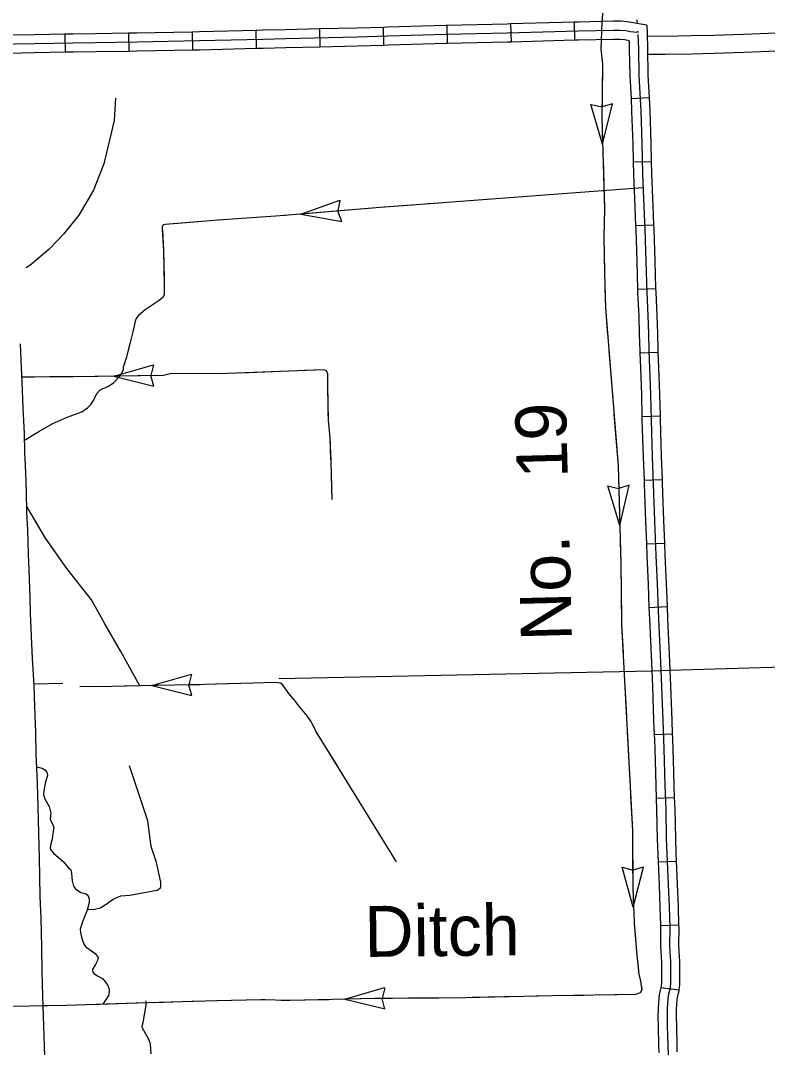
# Model space of a CAD drawing. Extents: x -117616 to 64730, y 54117 to 789866.
# Drawn here: x 62461.2 to 62585, y 54561.1 to 54731.4 of the extents above; entities that cross this region are included whole.
import ezdxf

# ---------------------------------------------------------------- set-up
doc = ezdxf.new("R2010")
doc.units = 0
for name, color, linetype in [('10', 7, 'Continuous'), ('32', 7, 'Continuous'), ('34', 7, 'Continuous'), ('35', 7, 'Continuous'), ('43', 7, 'Continuous'), ('46', 7, 'Continuous'), ('5', 7, 'Continuous')]:
    doc.layers.add(name, color=color, linetype=linetype)

msp = doc.modelspace()

# ---------------------------------------------------------------- linework, layer by layer
at = {"layer": '10'}
for points in [[(62463.45, 54621.13), (62463.17, 54625.64), (62463.03, 54629.31), (62462.86, 54633.17), (62462.8, 54635.73), (62462.61, 54640.27), (62462.52, 54642.92), (62462.37, 54646.97), (62462.25, 54649.9), (62462.17, 54653.28), (62462.08, 54656.55), (62461.9, 54659.8), (62461.85, 54662.96), (62461.61, 54667.13), (62461.46, 54671.55), (62461.34, 54673.84), (62461.16, 54677.81)], [(62465.35, 54556.4), (62465.1, 54562.98), (62464.96, 54568.04), (62464.9, 54569.68), (62464.75, 54573.76), (62464.71, 54577.71), (62464.61, 54582.54), (62464.45, 54586.14), (62464.37, 54589.4), (62464.35, 54592.54), (62464.23, 54596.68), (62464.1, 54600.96), (62464.01, 54604.98), (62463.8, 54609.81), (62463.73, 54613.37), (62463.56, 54617.65), (62463.45, 54621.13)]]:
    msp.add_lwpolyline(points, dxfattribs=at)
at = {"layer": '32'}
for p, q in [((62542.41, 54730.87), (62542.49, 54727.87)), ((62552.96, 54731.16), (62553.04, 54728.16)), ((62468.52, 54729.17), (62468.57, 54726.17)), ((62479.08, 54729.33), (62479.13, 54726.33)), ((62489.64, 54729.53), (62489.69, 54726.53)), ((62500.18, 54729.79), (62500.26, 54726.79)), ((62510.74, 54730.04), (62510.81, 54727.04)), ((62521.29, 54730.31), (62521.38, 54727.31)), ((62531.85, 54730.63), (62531.92, 54727.63)), ((62563.54, 54729.7), (62563.54, 54729.47)), ((62562.38, 54718.51), (62565.38, 54718.67)), ((62562.75, 54708), (62565.75, 54708.08)), ((62563.14, 54697.42), (62566.13, 54697.55)), ((62563.46, 54686.89), (62566.46, 54686.97)), ((62563.85, 54676.33), (62566.85, 54676.43)), ((62564.19, 54665.79), (62567.19, 54665.86)), ((62564.54, 54655.21), (62567.54, 54655.33)), ((62564.93, 54644.66), (62567.93, 54644.78)), ((62565.35, 54634.11), (62568.35, 54634.23)), ((62565.84, 54623.56), (62568.83, 54623.68)), ((62566.23, 54613), (62569.23, 54613.13)), ((62566.56, 54602.46), (62569.56, 54602.56)), ((62566.88, 54591.89), (62569.87, 54592.02)), ((62567.27, 54581.36), (62570.27, 54581.45)), ((62567.34, 54571.06), (62570.32, 54570.66))]:
    msp.add_line(p, q, dxfattribs=at)
for points in [[(62542.41, 54730.87), (62541.84, 54730.86), (62531.85, 54730.63)], [(62552.96, 54731.16), (62542.41, 54730.87)], [(62565.03, 54730.67), (62561.73, 54731.2), (62560.7, 54731.31), (62559.46, 54731.31), (62553.62, 54731.18), (62552.96, 54731.16)], [(62563.54, 54729.47), (62562.84, 54729.52), (62562.32, 54729.58), (62561.53, 54729.71), (62560.61, 54729.81), (62559.48, 54729.81), (62553.66, 54729.68), (62541.88, 54729.36), (62531.73, 54729.12), (62522.09, 54728.84), (62516.97, 54728.68), (62505.15, 54728.41), (62501.37, 54728.32), (62490.87, 54728.05), (62480.51, 54727.85), (62473.64, 54727.75), (62469.9, 54727.69), (62463.5, 54727.58), (62456.91, 54727.46)], [(62468.52, 54729.17), (62463.47, 54729.08), (62459.35, 54729)], [(62479.08, 54729.33), (62473.62, 54729.25), (62469.88, 54729.19), (62468.52, 54729.17)], [(62489.64, 54729.53), (62480.48, 54729.35), (62479.08, 54729.33)], [(62500.18, 54729.79), (62490.84, 54729.55), (62489.64, 54729.53)], [(62510.74, 54730.04), (62505.11, 54729.91), (62501.33, 54729.82), (62500.18, 54729.79)], [(62521.29, 54730.31), (62516.93, 54730.18), (62510.74, 54730.04)], [(62531.85, 54730.63), (62531.69, 54730.62), (62522.04, 54730.34), (62521.29, 54730.31)], [(62563.54, 54729.15), (62563.6, 54726.77), (62563.68, 54722.31), (62563.99, 54716.44), (62564.17, 54711.08), (62564.3, 54706.01), (62564.5, 54700.6), (62564.67, 54696.77), (62564.84, 54691.51), (62564.98, 54686.33), (62565.18, 54682.51), (62565.26, 54679.45), (62565.34, 54676.67), (62565.43, 54673.83), (62565.61, 54669.44), (62565.7, 54665.22), (62565.88, 54659.09), (62566.07, 54654.57), (62566.29, 54648.48), (62566.51, 54642.7), (62566.7, 54637.99), (62566.93, 54632.15), (62567.23, 54626.23), (62567.44, 54621.01), (62567.63, 54615.35), (62567.76, 54612.32), (62567.88, 54608.73), (62568, 54604.58), (62568.13, 54600.59), (62568.23, 54595.75), (62568.32, 54593.21), (62568.54, 54588.15), (62568.68, 54584.43), (62568.79, 54580.94), (62568.75, 54577.99), (62568.94, 54575.33), (62568.94, 54572.54), (62568.93, 54571.64), (62568.88, 54571.22), (62568.81, 54570.72), (62568.67, 54570.19), (62568.54, 54569.65), (62568.5, 54569.17), (62568.36, 54567.55), (62568.35, 54566), (62568.4, 54564.76), (62568.46, 54561.4), (62568.58, 54558.43)], [(62565.03, 54730.67), (62565.04, 54729.19)], [(62565.04, 54729.19), (62565.1, 54726.8), (62565.18, 54722.36), (62565.38, 54718.67)], [(62531.92, 54727.63), (62531.77, 54727.63), (62522.13, 54727.34), (62521.38, 54727.31)], [(62542.49, 54727.87), (62541.91, 54727.86), (62531.92, 54727.63)], [(62553.04, 54728.16), (62542.49, 54727.87)], [(62562.07, 54728.1), (62561.33, 54728.22), (62560.53, 54728.31), (62559.49, 54728.31), (62553.7, 54728.18), (62553.04, 54728.16)], [(62562.07, 54728.1), (62562.1, 54726.73), (62562.18, 54722.25), (62562.38, 54718.51)], [(62468.57, 54726.17), (62463.52, 54726.08), (62459.43, 54726)], [(62479.13, 54726.33), (62473.66, 54726.25), (62469.93, 54726.19), (62468.57, 54726.17)], [(62489.69, 54726.53), (62480.54, 54726.35), (62479.13, 54726.33)], [(62500.26, 54726.79), (62490.9, 54726.55), (62489.69, 54726.53)], [(62510.81, 54727.04), (62505.18, 54726.91), (62501.41, 54726.82), (62500.26, 54726.79)], [(62521.38, 54727.31), (62517.01, 54727.18), (62510.81, 54727.04)], [(62562.38, 54718.51), (62562.49, 54716.38), (62562.67, 54711.03), (62562.75, 54708)], [(62565.38, 54718.67), (62565.49, 54716.51), (62565.67, 54711.12), (62565.75, 54708.08)], [(62562.75, 54708), (62562.8, 54705.96), (62563, 54700.54), (62563.14, 54697.42)], [(62565.75, 54708.08), (62565.8, 54706.05), (62566, 54700.66), (62566.13, 54697.55)], [(62563.14, 54697.42), (62563.17, 54696.71), (62563.34, 54691.46), (62563.46, 54686.89)], [(62566.13, 54697.55), (62566.17, 54696.83), (62566.33, 54691.55), (62566.46, 54686.97)], [(62563.46, 54686.89), (62563.48, 54686.27), (62563.69, 54682.45), (62563.76, 54679.41), (62563.84, 54676.63), (62563.85, 54676.33)], [(62566.46, 54686.97), (62566.48, 54686.39), (62566.68, 54682.57), (62566.76, 54679.49), (62566.84, 54676.72), (62566.85, 54676.43)], [(62563.85, 54676.33), (62563.93, 54673.78), (62564.11, 54669.39), (62564.19, 54665.79)], [(62566.85, 54676.43), (62566.93, 54673.89), (62567.11, 54669.48), (62567.19, 54665.86)], [(62564.19, 54665.79), (62564.2, 54665.18), (62564.39, 54659.03), (62564.54, 54655.21)], [(62567.19, 54665.86), (62567.2, 54665.26), (62567.38, 54659.14), (62567.54, 54655.33)], [(62564.54, 54655.21), (62564.57, 54654.52), (62564.79, 54648.42), (62564.93, 54644.66)], [(62567.54, 54655.33), (62567.56, 54654.63), (62567.79, 54648.53), (62567.93, 54644.78)], [(62564.93, 54644.66), (62565.01, 54642.64), (62565.2, 54637.93), (62565.35, 54634.11)], [(62567.93, 54644.78), (62568.01, 54642.76), (62568.2, 54638.05), (62568.35, 54634.23)], [(62565.35, 54634.11), (62565.44, 54632.09), (62565.73, 54626.16), (62565.84, 54623.56)], [(62568.35, 54634.23), (62568.43, 54632.22), (62568.73, 54626.29), (62568.83, 54623.68)], [(62565.84, 54623.56), (62565.94, 54620.96), (62566.13, 54615.29), (62566.23, 54613)], [(62568.83, 54623.68), (62568.94, 54621.07), (62569.13, 54615.4), (62569.23, 54613.13)], [(62566.23, 54613), (62566.26, 54612.27), (62566.38, 54608.69), (62566.5, 54604.54), (62566.56, 54602.46)], [(62569.23, 54613.13), (62569.26, 54612.38), (62569.38, 54608.78), (62569.5, 54604.63), (62569.56, 54602.56)], [(62566.56, 54602.46), (62566.63, 54600.55), (62566.73, 54595.71), (62566.82, 54593.15), (62566.88, 54591.89)], [(62569.56, 54602.56), (62569.63, 54600.63), (62569.73, 54595.79), (62569.82, 54593.27), (62569.87, 54592.02)], [(62566.88, 54591.89), (62567.04, 54588.09), (62567.18, 54584.38), (62567.27, 54581.36)], [(62569.87, 54592.02), (62570.04, 54588.21), (62570.18, 54584.48), (62570.27, 54581.45)], [(62567.27, 54581.36), (62567.29, 54580.93), (62567.25, 54577.94), (62567.44, 54575.27), (62567.44, 54572.55), (62567.43, 54571.75), (62567.39, 54571.4), (62567.34, 54571.06)], [(62570.27, 54581.45), (62570.29, 54580.95), (62570.25, 54578.03), (62570.44, 54575.38), (62570.44, 54572.53), (62570.43, 54571.54), (62570.37, 54571.03), (62570.32, 54570.66)], [(62567.34, 54571.06), (62567.34, 54571.02), (62567.22, 54570.56), (62567.05, 54569.88), (62567.01, 54569.29), (62566.86, 54567.62), (62566.85, 54565.98), (62566.9, 54564.71), (62566.96, 54561.36), (62567.01, 54560.29)], [(62570.32, 54570.66), (62570.29, 54570.43), (62570.12, 54569.82), (62570.03, 54569.41), (62570, 54569.04), (62569.86, 54567.47), (62569.85, 54566.03), (62569.9, 54564.8), (62569.96, 54561.44), (62570, 54560.4)]]:
    msp.add_lwpolyline(points, dxfattribs=at)
at = {"layer": '34'}
msp.add_lwpolyline([(62563.45, 54730.92), (62563.4, 54731.57)], dxfattribs=at)
at = {"layer": '35'}
for points in [[(62476.94, 54718.55), (62476.69, 54714.86), (62474.97, 54707.66), (62473.31, 54703.29), (62470.85, 54699.17), (62468.33, 54696.03), (62465.87, 54693.45), (62462.98, 54691.05), (62462.12, 54690.43)], [(62461.87, 54661.82), (62464.24, 54663.28), (62466.41, 54664.56), (62468.89, 54665.64), (62471.34, 54666.53), (62472.3, 54667.21), (62472.85, 54667.75), (62473.3, 54668.44), (62473.61, 54669.12), (62473.87, 54669.66), (62474.36, 54670.15), (62474.81, 54670.43), (62475.32, 54670.58), (62475.78, 54670.78), (62476.63, 54671.43), (62477.69, 54672.52), (62478.23, 54673.51), (62478.27, 54674.09)], [(62480.97, 54621.11), (62477.82, 54626.81), (62475.18, 54631.37), (62472.96, 54635.37), (62468.84, 54640.55), (62465.31, 54645.57), (62462.23, 54650.86)], [(62463.89, 54607.66), (62464.77, 54607.44), (62465.22, 54607.18), (62465.54, 54606.8), (62465.63, 54606.2), (62465.35, 54605.15), (62465.05, 54603.75), (62465.01, 54603.09), (62465.24, 54602.36), (62465.93, 54601.09), (62466.2, 54599.97), (62466.12, 54598.91), (62466.51, 54598.18), (62466.68, 54597.58), (62466.61, 54596.94), (62466.44, 54595.7), (62466.21, 54594.9), (62466.12, 54594.16), (62466.29, 54593.77), (62466.66, 54593.34), (62468.24, 54591.97)], [(62472.27, 54583.97), (62473.44, 54584.06), (62474.37, 54584.26), (62475.23, 54584.77), (62476.55, 54585.7), (62477.8, 54586.25), (62479.32, 54586.4), (62482, 54586.87), (62483.84, 54587.22), (62484.42, 54587.65), (62484.46, 54588.51), (62483.72, 54591.78), (62482.82, 54594.44), (62482.28, 54598.69), (62480.45, 54604.18), (62479.24, 54607.81)], [(62468.24, 54591.97), (62469.14, 54590.91), (62469.51, 54590.56), (62469.66, 54589.96), (62469.75, 54588.75), (62469.96, 54587.89), (62470.31, 54587.4), (62471.19, 54586.82), (62471.95, 54586.64), (62472.36, 54586.36), (62472.55, 54585.78), (62472.55, 54585.16), (62472.25, 54583.9), (62471.49, 54582.1), (62471.09, 54580.72), (62471.13, 54580.2), (62471.34, 54579.21), (62471.69, 54578.24), (62471.97, 54577.87), (62472.79, 54577.25), (62473.57, 54576.71), (62474.04, 54576.02), (62473.93, 54575.54), (62473.63, 54574.85), (62473.12, 54574.1), (62473.09, 54573.77), (62473.33, 54573.38), (62473.96, 54572.99), (62474.8, 54572.54), (62475.27, 54571.97), (62475.66, 54571.38), (62475.9, 54570.72), (62475.9, 54570.36), (62475.75, 54569.73), (62475.36, 54569.13), (62474.84, 54568.27)], [(62482.82, 54560.06), (62482.72, 54561.68), (62482.48, 54562.46), (62481.9, 54563.45), (62481.6, 54563.95), (62481.39, 54564.29), (62481.36, 54564.67), (62481.53, 54565.24), (62482.04, 54568.12), (62482.04, 54568.87)]]:
    msp.add_lwpolyline(points, dxfattribs=at)
at = {"layer": '43'}
for p, q in [((62555.74, 54717.54), (62557.58, 54717.11)), ((62557.68, 54710.96), (62555.74, 54717.54)), ((62559.29, 54717.63), (62557.6, 54717.11)), ((62557.68, 54710.96), (62559.29, 54717.63)), ((62507.67, 54699.35), (62514.13, 54701.65)), ((62514.13, 54701.65), (62513.8, 54699.85)), ((62507.67, 54699.35), (62514.42, 54698.11)), ((62514.42, 54698.11), (62513.81, 54699.83)), ((62476.63, 54672.46), (62483.23, 54674.34)), ((62483.23, 54674.34), (62482.79, 54672.57)), ((62476.63, 54672.46), (62483.29, 54670.79)), ((62483.29, 54670.79), (62482.79, 54672.54)), ((62560.52, 54647.69), (62558.55, 54654.27)), ((62558.55, 54654.27), (62560.33, 54653.85)), ((62562.1, 54654.37), (62560.35, 54653.85)), ((62560.52, 54647.69), (62562.1, 54654.37)), ((62482.93, 54621.14), (62489.53, 54623.02)), ((62489.53, 54623.03), (62489.09, 54621.26)), ((62482.93, 54621.14), (62489.59, 54619.47)), ((62489.59, 54619.48), (62489.09, 54621.23)), ((62562.72, 54584.38), (62560.89, 54591)), ((62560.89, 54591), (62562.66, 54590.54)), ((62564.44, 54591.03), (62562.68, 54590.54)), ((62562.72, 54584.38), (62564.44, 54591.03)), ((62514.95, 54569.11), (62521.53, 54571.06)), ((62521.57, 54571.03), (62521.11, 54569.26)), ((62514.95, 54569.11), (62521.62, 54567.5)), ((62521.59, 54567.47), (62521.11, 54569.23))]:
    msp.add_line(p, q, dxfattribs=at)
for points in [[(62557.87, 54735.19), (62557.57, 54731.24), (62557.37, 54726.69), (62557.67, 54724.22), (62557.57, 54715.33), (62557.96, 54700.12), (62557.87, 54695.57), (62557.96, 54689.55), (62558.16, 54683.72), (62560.23, 54657.64), (62560.7, 54641.38), (62560.82, 54631.27), (62562.61, 54597.12), (62562.69, 54587.57), (62562.92, 54581.79), (62563.31, 54576.99), (62563.69, 54573.27), (62563.98, 54572.11), (62564.09, 54571.33), (62564.15, 54570.69), (62563.92, 54570.19), (62563.12, 54569.88), (62549.35, 54569.67), (62535, 54569.37), (62530.54, 54569.31), (62519.98, 54569.24), (62505.82, 54568.88), (62501.04, 54569.04), (62493.73, 54568.85), (62480.38, 54568.45), (62468.72, 54568.06), (62459.7, 54567.93)], [(62557.44, 54728.26), (62557.37, 54726.69), (62557.67, 54724.22), (62557.64, 54721.51)], [(62557.61, 54718.87), (62557.57, 54715.33), (62557.68, 54710.96)], [(62557.75, 54708.32), (62557.85, 54704.36)], [(62564.26, 54703.68), (62528.96, 54701.03), (62520.81, 54700.41), (62504.24, 54699.07), (62493.23, 54698.26), (62485.17, 54697.61), (62484.9, 54697.55), (62484.78, 54697.43), (62484.69, 54697.19), (62484.69, 54696.84), (62484.9, 54693.23), (62485.02, 54687.63), (62485.02, 54685.97), (62484.84, 54685.58), (62484.19, 54684.98), (62481.87, 54683.47), (62480.74, 54682.51), (62480.41, 54682.13), (62480.2, 54681.59), (62479.78, 54679.8), (62478.74, 54675.6), (62478.27, 54674.09)], [(62557.85, 54704.36), (62557.96, 54700.4)], [(62526.09, 54700.81), (62520.81, 54700.41), (62518.19, 54700.2)], [(62530.55, 54701.15), (62528.96, 54701.03), (62528.72, 54701.02)], [(62501.09, 54698.84), (62497.14, 54698.55)], [(62505.04, 54699.13), (62504.24, 54699.07), (62501.09, 54698.84)], [(62515.56, 54699.98), (62507.67, 54699.35)], [(62494.51, 54698.36), (62493.23, 54698.26), (62486.61, 54697.73)], [(62557.91, 54697.76), (62557.87, 54695.57), (62557.96, 54689.84)], [(62484.7, 54696.7), (62484.9, 54693.23), (62485, 54688.78)], [(62558.04, 54687.2), (62558.16, 54683.72), (62558.51, 54679.3)], [(62485.02, 54686.14), (62485.02, 54685.97), (62484.84, 54685.58), (62484.19, 54684.98), (62481.87, 54683.47), (62480.74, 54682.51), (62480.41, 54682.13), (62480.2, 54681.59), (62479.95, 54680.52)], [(62479.33, 54677.95), (62478.74, 54675.6), (62478.27, 54674.09)], [(62558.72, 54676.67), (62559.35, 54668.77)], [(62512.82, 54651.98), (62512.66, 54658.37), (62512.51, 54662.25), (62512.23, 54665.15), (62512.11, 54670.92), (62512.11, 54672.83), (62511.89, 54673.33), (62511.46, 54673.51), (62494.01, 54672.84), (62486.2, 54672.9), (62484.91, 54672.59), (62473.48, 54672.41), (62461.43, 54672.28)], [(62505.62, 54673.29), (62497.71, 54672.98)], [(62512.15, 54669.12), (62512.11, 54670.92), (62512.11, 54672.83), (62511.89, 54673.33), (62511.46, 54673.51), (62508.26, 54673.39)], [(62463.43, 54672.3), (62461.43, 54672.28)], [(62470.03, 54672.37), (62466.07, 54672.33)], [(62473.99, 54672.41), (62473.48, 54672.41), (62470.03, 54672.37)], [(62484.55, 54672.58), (62476.63, 54672.46)], [(62495.07, 54672.88), (62494.01, 54672.84), (62487.15, 54672.89)], [(62512.65, 54658.58), (62512.51, 54662.25), (62512.23, 54665.15), (62512.2, 54666.49)], [(62559.56, 54666.14), (62560.19, 54658.25)], [(62512.82, 54651.98), (62512.72, 54655.94)], [(62560.29, 54655.61), (62560.52, 54647.69)], [(62560.59, 54645.05), (62560.7, 54641.38), (62560.7, 54641.09)], [(62560.7, 54641.09), (62560.75, 54637.13)], [(62560.78, 54634.49), (62560.82, 54631.27), (62561.06, 54626.58)], [(62561.2, 54623.94), (62561.62, 54616.04)], [(62523.49, 54591.91), (62512.42, 54609.91), (62511.13, 54611.99), (62510.16, 54613.55), (62509.41, 54615.06), (62508.71, 54616.14), (62507.31, 54617.75), (62506.63, 54618.67), (62505.67, 54619.83), (62504.83, 54621.01), (62504.54, 54621.36), (62504.27, 54621.55), (62503.86, 54621.61), (62503.38, 54621.66), (62499.73, 54621.56), (62491.69, 54621.29), (62486.72, 54621.2), (62481.17, 54621.11), (62476.37, 54620.98), (62471.04, 54620.93)], [(62476.34, 54620.98), (62472.38, 54620.95)], [(62480.29, 54621.09), (62476.37, 54620.98), (62476.34, 54620.98)], [(62490.85, 54621.28), (62486.72, 54621.2), (62482.93, 54621.14)], [(62501.41, 54621.6), (62499.73, 54621.56), (62493.49, 54621.35)], [(62509.07, 54615.57), (62508.71, 54616.14), (62507.31, 54617.75), (62506.63, 54618.67), (62505.67, 54619.83), (62504.83, 54621.01), (62504.54, 54621.36), (62504.27, 54621.55), (62504.04, 54621.58)], [(62561.75, 54613.4), (62562.17, 54605.49)], [(62513.71, 54607.81), (62512.42, 54609.91), (62511.13, 54611.99), (62510.34, 54613.26)], [(62562.31, 54602.85), (62562.61, 54597.12), (62562.63, 54594.94)], [(62562.65, 54592.3), (62562.69, 54587.57), (62562.82, 54584.38)], [(62562.93, 54581.75), (62563.24, 54577.8)], [(62563.24, 54577.8), (62563.31, 54576.99), (62563.63, 54573.86)], [(62564.1, 54571.26), (62564.15, 54570.69), (62563.92, 54570.19), (62563.12, 54569.88), (62557.18, 54569.79)], [(62501.76, 54569.02), (62501.04, 54569.04), (62493.84, 54568.85)], [(62512.31, 54569.04), (62508.35, 54568.94)], [(62522.87, 54569.26), (62519.98, 54569.24), (62514.95, 54569.11)], [(62533.43, 54569.35), (62530.54, 54569.31), (62525.51, 54569.27)], [(62543.99, 54569.56), (62536.07, 54569.39)], [(62554.55, 54569.75), (62549.35, 54569.67), (62546.63, 54569.61)], [(62470.09, 54568.11), (62468.72, 54568.06), (62464.96, 54568)], [(62480.65, 54568.46), (62480.38, 54568.45), (62472.73, 54568.19)], [(62491.2, 54568.77), (62483.28, 54568.54)], [(62508.35, 54568.94), (62505.82, 54568.88), (62504.4, 54568.93)]]:
    msp.add_lwpolyline(points, dxfattribs=at)
at = {"layer": '46'}
for points in [[(62565.05, 54728.88), (62568.04, 54728.87), (62572.37, 54728.94), (62576.1, 54729.01), (62581.04, 54729.19), (62587.9, 54729.44), (62589.52, 54729.51), (62590.13, 54729.47), (62590.65, 54729.29), (62590.15, 54727.87), (62589.65, 54726.46)], [(62565.12, 54725.88), (62568.06, 54725.87), (62572.42, 54725.94), (62576.18, 54726.01), (62581.15, 54726.2), (62588.01, 54726.45), (62589.49, 54726.51), (62589.52, 54726.5), (62589.65, 54726.46)]]:
    msp.add_lwpolyline(points, dxfattribs=at)
at = {"layer": '5'}
for points in [[(62657.22, 54626.24), (62568.84, 54623.62)], [(62565.84, 54623.53), (62504.03, 54622.23)], [(62468.19, 54621.47), (62463.43, 54621.37)]]:
    msp.add_lwpolyline(points, dxfattribs=at)

# ---------------------------------------------------------------- texts
at = {"layer": '43'}
for s, rotation, p in [('No.   19', 91.4673, (62552.6, 54628.62)), ('Ditch', 0.6747, (62518.23, 54576.12))]:
    msp.add_text(s, height=8.448, rotation=rotation, dxfattribs=at).set_placement(p)

doc.saveas('drawing.dxf')
